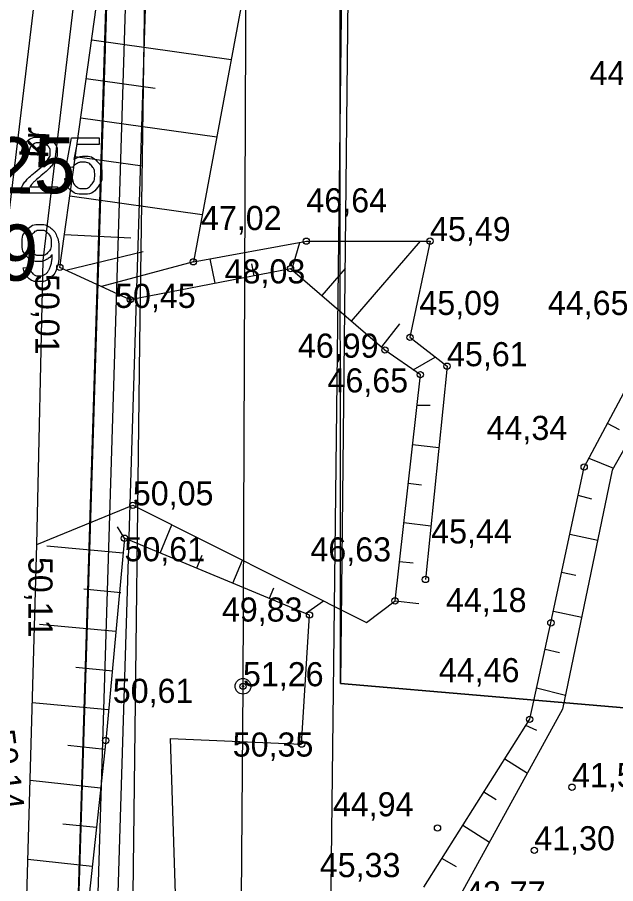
# Model space of a CAD drawing. Extents: x 700746 to 706058, y 6570320 to 6580460.
# Drawn here: x 702833.2 to 702894, y 6575690.9 to 6575779 of the extents above; entities that cross this region are included whole.
import ezdxf

# ---------------------------------------------------------------- set-up
doc = ezdxf.new("R2010")
doc.units = 0
for name, color, linetype in [('illumineerimisjooned', 7, 'Continuous'), ('Kaitsevöönd', 7, 'Continuous'), ('kataster', 7, 'Continuous'), ('KORGUS-EH2000', 7, 'Continuous'), ('KPKAABEL', 7, 'Continuous'), ('Plokid', 7, 'Continuous'), ('POST', 7, 'Continuous'), ('RELJEEF', 7, 'Continuous'), ('TEE', 7, 'Continuous'), ('Tmaad_maeeraldised_kehtivad', 7, 'Continuous'), ('VEEKOGU', 7, 'Continuous'), ('VWX2_MV_PLOKK', 7, 'Continuous')]:
    doc.layers.add(name, color=color, linetype=linetype)

msp = doc.modelspace()

# ---------------------------------------------------------------- linework, layer by layer
at = {"layer": 'illumineerimisjooned'}
msp.add_lwpolyline([(703275.453, 6577071.675), (703358.033, 6576531.935), (703309.575, 6576228.785), (703291.689, 6575965.796), (703292.021, 6575933.773), (703296.797, 6575575.058), (702854.003, 6575511.215), (702839.234, 6575620.766), (702850.34, 6575977.305), (702784.776, 6576064.061), (702784.616, 6576095.834), (702844.434, 6576209.852), (702855.457, 6576267.302), (702846.533, 6576489.405), (702878.886, 6576547.086), (702976.891, 6576643.26), (702915.328, 6577059.558)], dxfattribs=at)
at = {"layer": 'Kaitsevöönd'}
for points in [[(702808.735, 6576109.925), (702830.035, 6576060.935), (702864.499, 6575987.242), (702865.476, 6575983.196), (702867.41, 6575887.926), (702864.438, 6575639.035), (702863.499, 6575550.311), (702871.746, 6575516.763), (703096.25, 6575553.857)], [(703057.554, 6575527.213), (702948.271, 6575509.249), (702866.405, 6575495.727), (702861.964, 6575495.437), (702858.681, 6575497.176), (702855.689, 6575499.88), (702853.951, 6575503.84), (702843.235, 6575549.524), (702845.069, 6575698.167), (702845.649, 6575745.879), (702846.421, 6575800.352), (702847.193, 6575873.756), (702847.193, 6575901.669), (702846.517, 6575932.865), (702845.542, 6575980.609), (702820.936, 6576032.471), (702787.754, 6576109.144)]]:
    msp.add_lwpolyline(points, dxfattribs=at)
at = {"layer": 'kataster'}
msp.add_lwpolyline([(702852.27, 6575508.89), (702837.26, 6575620.73), (702848.38, 6575976.59), (702782.85, 6576063.35), (702782.57, 6576096.37), (702842.53, 6576210.56), (702853.4, 6576267.5), (702844.46, 6576489.93), (702877.29, 6576548.25), (702974.72, 6576643.9), (702913.57, 6577058.07), (702784.04, 6577102.84), (702746.48, 6577248.7), (702719.69, 6577297.36), (702713.81, 6577334.91), (703089.87, 6577211.79), (703231.53, 6577106.55), (703277.36, 6577072.83), (703360.09, 6576531.99), (703311.6, 6576228.52), (703293.62, 6575965.66), (703298.84, 6575573.29)], close=True, dxfattribs=at)
for points in [[(702782.57, 6576096.37), (702782.85, 6576063.35), (702848.38, 6575976.59), (702837.26, 6575620.73), (702852.27, 6575508.89), (703298.84, 6575573.29), (703375.63, 6575584.41), (703375.41, 6575624), (703375.74, 6575634.8), (703375.62, 6575689.75), (703370.21, 6575799.42), (703370.29, 6575828.47), (703365.86, 6576033.99), (703361.97, 6576073.22), (703340.19, 6576155.31)], [(702838.794, 6575763.726), (702838.138, 6575763.813), (702838.69, 6575766.741), (702841.522, 6575766.741), (702841.522, 6575766.072), (702839.249, 6575766.072), (702838.942, 6575764.542)], [(702834.345, 6575765.117), (702833.624, 6575765.19)], [(702838.012, 6575762.61), (702838.746, 6575762.671)], [(702837.26, 6575761.789), (702837.26, 6575761.115), (702833.494, 6575761.115)], [(702834.467, 6575761.789), (702837.26, 6575761.789)], [(702833.779, 6575753.559), (702834.452, 6575753.62)]]:
    msp.add_lwpolyline(points, dxfattribs=at)
for points in [[(702833.494, 6575761.115), (702833.486, 6575761.368), (702833.575, 6575761.602), (702833.719, 6575761.987), (702834.037, 6575762.36), (702834.354, 6575762.733), (702834.952, 6575763.222), (702835.88, 6575763.985), (702836.205, 6575764.43), (702836.531, 6575764.875), (702836.531, 6575765.272), (702836.531, 6575765.688), (702836.234, 6575765.974), (702835.937, 6575766.259), (702835.459, 6575766.259), (702834.955, 6575766.259), (702834.652, 6575765.956), (702834.349, 6575765.653), (702834.345, 6575765.117)], [(702833.624, 6575765.19), (702833.698, 6575765.994), (702834.18, 6575766.416), (702834.662, 6575766.837), (702835.475, 6575766.837), (702836.295, 6575766.837), (702836.773, 6575766.382), (702837.252, 6575765.928), (702837.252, 6575765.255), (702837.252, 6575764.913), (702837.112, 6575764.583), (702836.972, 6575764.253), (702836.648, 6575763.888), (702836.324, 6575763.522), (702835.571, 6575762.885), (702834.941, 6575762.356), (702834.762, 6575762.168), (702834.583, 6575761.979), (702834.467, 6575761.789)], [(702838.942, 6575764.542), (702839.455, 6575764.899), (702840.019, 6575764.899), (702840.765, 6575764.899), (702841.279, 6575764.382), (702841.792, 6575763.864), (702841.792, 6575763.051), (702841.792, 6575762.277), (702841.341, 6575761.712), (702840.792, 6575761.02), (702839.844, 6575761.02), (702839.066, 6575761.02), (702838.574, 6575761.455), (702838.082, 6575761.891), (702838.012, 6575762.61)], [(702838.746, 6575762.671), (702838.828, 6575762.134), (702839.124, 6575761.863), (702839.421, 6575761.593), (702839.843, 6575761.593), (702840.352, 6575761.593), (702840.7, 6575761.975), (702841.049, 6575762.357), (702841.049, 6575762.988), (702841.049, 6575763.589), (702840.714, 6575763.936), (702840.379, 6575764.282), (702839.832, 6575764.282), (702839.492, 6575764.282), (702839.221, 6575764.128), (702838.95, 6575763.973), (702838.794, 6575763.726)], [(702834.452, 6575753.62), (702834.538, 6575753.145), (702834.779, 6575752.93), (702835.019, 6575752.716), (702835.396, 6575752.716), (702835.718, 6575752.716), (702835.962, 6575752.864), (702836.206, 6575753.012), (702836.36, 6575753.259), (702836.514, 6575753.506), (702836.619, 6575753.926), (702836.724, 6575754.346), (702836.724, 6575754.782), (702836.724, 6575754.829), (702836.72, 6575754.922), (702836.511, 6575754.587), (702836.147, 6575754.379), (702835.784, 6575754.171), (702835.361, 6575754.171), (702834.654, 6575754.171), (702834.164, 6575754.684), (702833.675, 6575755.197), (702833.675, 6575756.037), (702833.675, 6575756.903), (702834.186, 6575757.431), (702834.696, 6575757.96), (702835.466, 6575757.96), (702836.021, 6575757.96), (702836.482, 6575757.661), (702836.942, 6575757.361), (702837.181, 6575756.808), (702837.42, 6575756.254), (702837.42, 6575755.205), (702837.42, 6575754.113), (702837.183, 6575753.466), (702836.946, 6575752.819), (702836.478, 6575752.481), (702836.009, 6575752.143), (702835.38, 6575752.143), (702834.712, 6575752.143), (702834.288, 6575752.514), (702833.864, 6575752.886), (702833.779, 6575753.559)], [(702836.642, 6575756.072), (702836.642, 6575756.674), (702836.323, 6575757.028), (702836.004, 6575757.382), (702835.552, 6575757.382), (702835.084, 6575757.382), (702834.74, 6575757.001), (702834.396, 6575756.62), (702834.396, 6575756.013), (702834.396, 6575755.469), (702834.723, 6575755.129), (702835.049, 6575754.788), (702835.533, 6575754.788), (702836.017, 6575754.788), (702836.33, 6575755.129), (702836.642, 6575755.469), (702836.642, 6575756.072)]]:
    msp.add_open_spline(points, degree=3, dxfattribs=at)
at = {"layer": 'KORGUS-EH2000'}
for centre in [(702862.577, 6575756.254), (702875.146, 6575756.258), (702837.505, 6575753.588), (702851.08, 6575754.152), (702860.956, 6575753.455), (702844.673, 6575750.305), (702873.104, 6575746.479), (702870.565, 6575745.185), (702876.87, 6575743.541), (702874.162, 6575742.673), (702890.814, 6575733.297), (702844.929, 6575729.402), (702844.078, 6575726.057), (702874.68, 6575721.867), (702871.589, 6575719.69), (702862.888, 6575718.244), (702887.432, 6575717.455), (702856.125, 6575711.01), (702885.279, 6575707.657), (702842.17, 6575705.495), (702862.086, 6575705.125), (702889.577, 6575700.75), (702875.904, 6575696.596), (702885.74, 6575694.338)]:
    msp.add_circle(centre, 0.32, dxfattribs=at)
at = {"layer": 'KPKAABEL'}
msp.add_lwpolyline([(702819.632, 6576245.483), (702836.589, 6576184.262), (702797.604, 6576109.544), (702828.991, 6576046.164), (702858.934, 6575984.917), (702857.418, 6575888.76), (702856.506, 6575810.457), (702856.125, 6575711.01), (702855.369, 6575615.968), (702854.387, 6575550.184), (702865.017, 6575505.159), (702921.92, 6575514.247), (702993.744, 6575525.722), (703056.422, 6575535.341), (703120.247, 6575545.359), (703173.195, 6575553.732), (703215.558, 6575560.468), (703265.052, 6575567.872), (703307.328, 6575597.7), (703332.603, 6575614.363)], dxfattribs=at)
at = {"layer": 'Plokid'}
for points in [[(702917.129, 6577061.05), (702979.018, 6576642.545), (702880.491, 6576545.858), (702848.554, 6576488.92), (702857.464, 6576267.152), (702846.343, 6576209.185), (702786.618, 6576095.345), (702786.772, 6576064.737), (702852.361, 6575977.948), (702841.238, 6575620.869), (702855.715, 6575513.483), (703019.069, 6575537.036)], [(703072.3, 6576854.63), (703101.31, 6576579.97), (703076.01, 6576303.02), (703067.36, 6576229.67), (703051.03, 6576091.21), (703059.38, 6575886.59), (702981.97, 6575701.33), (702866.03, 6575711.28), (702865.95, 6575985.44), (702842.72, 6576158.42), (702849.095, 6576223.528)]]:
    msp.add_lwpolyline(points, dxfattribs=at)
at = {"layer": 'POST'}
for radius in [0.8, 0.0747]:
    msp.add_circle((702856.125, 6575711.01), radius, dxfattribs=at)
at = {"layer": 'RELJEEF'}
for p, q in [((702840.747, 6575776.701), (702854.925, 6575774.713)), ((702847.19, 6575771.758), (702840.192, 6575772.74)), ((702839.636, 6575768.779), (702853.453, 6575766.841)), ((702845.898, 6575763.861), (702839.08, 6575764.818)), ((702838.525, 6575760.857), (702851.981, 6575758.969)), ((702844.717, 6575756.553), (702837.969, 6575756.895)), ((702861.101, 6575753.33), (702861.903, 6575756.131)), ((702867.165, 6575748.111), (702874.176, 6575756.258)), ((702838.106, 6575753.313), (702845.989, 6575755.191)), ((702851.08, 6575754.152), (702841.742, 6575751.647)), ((702853.29, 6575751.971), (702852.807, 6575754.468)), ((702857.003, 6575753.964), (702857.217, 6575752.731)), ((702866.515, 6575753.488), (702864.133, 6575750.72)), ((702872.037, 6575747.843), (702870.197, 6575745.502)), ((702873.446, 6575743.173), (702875.681, 6575744.468)), ((702875.141, 6575739.559), (702873.814, 6575739.565)), ((702894.406, 6575737.073), (702893.187, 6575737.726)), ((702873.369, 6575735.59), (702876.037, 6575735.292)), ((702891.298, 6575734.2), (702893.802, 6575733.18)), ((702874.279, 6575731.463), (702872.924, 6575731.615)), ((702891.594, 6575730.035), (702890.193, 6575730.387)), ((702872.479, 6575727.64), (702875.232, 6575727.332)), ((702843.324, 6575727.219), (702844.073, 6575725.998)), ((702847.717, 6575724.545), (702848.887, 6575727.419)), ((702889.358, 6575726.475), (702892.199, 6575725.869)), ((702843.937, 6575724.54), (702836.183, 6575725.26)), ((702851.952, 6575724.312), (702851.411, 6575723.011)), ((702855.106, 6575721.476), (702856.077, 6575723.816)), ((702873.432, 6575723.508), (702872.034, 6575723.665)), ((702889.953, 6575722.258), (702888.523, 6575722.564)), ((702839.956, 6575720.925), (702843.697, 6575720.545)), ((702859.231, 6575720.981), (702858.8, 6575719.942)), ((702862.494, 6575718.408), (702864.317, 6575719.688)), ((702871.589, 6575719.69), (702874.02, 6575719.417)), ((702887.688, 6575718.652), (702890.565, 6575718.031)), ((702843.198, 6575716.574), (702835.444, 6575717.294)), ((702888.292, 6575714.425), (702886.836, 6575714.743)), ((702839.146, 6575712.967), (702842.887, 6575712.586)), ((702885.978, 6575710.837), (702888.91, 6575710.093)), ((702842.459, 6575708.609), (702834.704, 6575709.328)), ((702886.013, 6575706.52), (702884.882, 6575707.027)), ((702838.336, 6575705.008), (702842.077, 6575704.627)), ((702882.748, 6575703.644), (702885.046, 6575702.194)), ((702841.649, 6575700.65), (702834.485, 6575701.42)), ((702881.865, 6575699.472), (702880.613, 6575700.261)), ((702837.797, 6575697.041), (702841.221, 6575696.673)), ((702878.479, 6575696.878), (702881.187, 6575695.169)), ((702840.793, 6575692.696), (702834.262, 6575693.398)), ((702877.841, 6575692.649), (702876.344, 6575693.496))]:
    msp.add_line(p, q, dxfattribs=at)
for points in [[(702871.589, 6575719.69), (702874.162, 6575742.673), (702870.565, 6575745.185), (702860.956, 6575753.455), (702844.673, 6575750.305), (702837.505, 6575753.588), (702842.098, 6575786.333), (702840.272, 6575807.444), (702853.436, 6575807.886), (702859.35, 6575808.801), (702870.938, 6575805.69), (702872.009, 6575807.48), (702858.699, 6575809.522), (702857.068, 6575811.593), (702851.253, 6575813.293), (702841.691, 6575818.092), (702843.708, 6575841.79), (702844.92, 6575862.739), (702851.277, 6575867.185), (702864.837, 6575861.887)], [(702865.774, 6575857.932), (702864.619, 6575855.386), (702866.231, 6575833.66), (702863.097, 6575820.039), (702879.935, 6575816.131), (702881.058, 6575800.72), (702871.833, 6575799.253), (702858.602, 6575794.375), (702851.08, 6575754.152), (702862.577, 6575756.254), (702875.146, 6575756.258), (702873.104, 6575746.479), (702876.87, 6575743.541), (702874.68, 6575721.867)], [(702874.512, 6575690.592), (702885.279, 6575707.657), (702887.432, 6575717.455), (702890.814, 6575733.297), (702897.026, 6575744.892), (702902.126, 6575769.488), (702911.243, 6575780.672), (702915.186, 6575790.449), (702915.469, 6575796.627), (702923.765, 6575822.645), (702908.57, 6575835.71)], [(702835.151, 6575725.409), (702844.929, 6575729.402), (702868.679, 6575717.503), (702871.589, 6575719.69)], [(702849.439, 6575684.65), (702848.745, 6575705.714), (702862.086, 6575705.125), (702862.888, 6575718.244), (702844.078, 6575726.057), (702842.17, 6575705.495), (702840.142, 6575686.638), (702843.776, 6575683.256), (702849.439, 6575684.65)]]:
    msp.add_lwpolyline(points, dxfattribs=at)
at = {"layer": 'TEE'}
for points in [[(702830.027, 6575684.968), (702831.152, 6575725.51), (702831.817, 6575754.565), (702835.347, 6575784.08), (702835.644, 6575813.072), (702839.086, 6575843.28), (702841.092, 6575866.647), (702842.664, 6575897.87), (702846.655, 6575935.935), (702841.574, 6575967.648), (702838.099, 6575974.634), (702830.651, 6575991.099), (702817.57, 6576005.083), (702798.577, 6576023.982), (702784.187, 6576040.099), (702774.299, 6576061.057), (702771.808, 6576073.949), (702774.342, 6576099.093)], [(702834.025, 6575684.858), (702835.151, 6575725.409), (702835.811, 6575754.281), (702839.345, 6575783.821), (702839.641, 6575812.824), (702843.066, 6575842.882), (702845.083, 6575866.375), (702846.653, 6575897.561), (702850.688, 6575936.045), (702845.427, 6575968.882), (702841.714, 6575976.348), (702834.023, 6575993.349), (702820.442, 6576007.868), (702801.482, 6576026.734), (702787.557, 6576042.33), (702778.131, 6576062.309), (702775.846, 6576074.132), (702778.245, 6576097.929)]]:
    msp.add_lwpolyline(points, dxfattribs=at)
at = {"layer": 'Tmaad_maeeraldised_kehtivad'}
msp.add_lwpolyline([(703277.305, 6577072.795), (703360.057, 6576531.928), (703311.564, 6576228.559), (703293.69, 6575965.739), (703294.021, 6575933.797), (703298.82, 6575573.329), (702852.291, 6575508.948), (702837.23, 6575620.663), (702848.319, 6575976.662), (702782.779, 6576063.386), (702782.613, 6576096.322), (702842.526, 6576210.519), (702853.449, 6576267.453), (702844.512, 6576489.89), (702877.282, 6576548.313), (702974.764, 6576643.974), (702913.527, 6577058.065)], dxfattribs=at)
at = {"layer": 'VEEKOGU'}
msp.add_lwpolyline([(702958.218, 6575889.272), (702958.059, 6575889.258), (702954.605, 6575888.27), (702948.294, 6575884.892), (702933.624, 6575863.588), (702930.278, 6575837.16), (702934.021, 6575828.451), (702932.487, 6575821.044), (702937.325, 6575809.272), (702934.599, 6575804.415), (702920.203, 6575795.023), (702917.021, 6575790.184), (702912.522, 6575779.383), (702904.861, 6575766.699), (702900.619, 6575756.999), (702900.7, 6575745.439), (702893.678, 6575732.96), (702888.619, 6575708.698), (702877.905, 6575689.195)], dxfattribs=at)
msp.add_lwpolyline([(702958.218, 6575889.272), (702958.059, 6575889.258), (702954.605, 6575888.27), (702948.294, 6575884.892), (702933.624, 6575863.588), (702930.278, 6575837.16), (702934.021, 6575828.451), (702932.487, 6575821.044), (702937.325, 6575809.272), (702934.599, 6575804.415), (702920.203, 6575795.023), (702917.021, 6575790.184), (702912.522, 6575779.383), (702904.861, 6575766.699), (702900.619, 6575756.999), (702900.7, 6575745.439), (702893.678, 6575732.96), (702888.619, 6575708.698), (702877.905, 6575689.195)], dxfattribs=at)
at = {"layer": 'VWX2_MV_PLOKK'}
msp.add_lwpolyline([(703145.59, 6575981.92), (703053.36, 6575698.14), (703018.17, 6575532.81), (702852.27, 6575508.89), (702837.26, 6575620.73), (702848.38, 6575976.59), (702782.85, 6576063.35), (702782.57, 6576096.37), (702842.53, 6576210.56), (702853.4, 6576267.5), (702842.72, 6576158.42), (702865.95, 6575985.44), (702867.94, 6575888.34), (702866.03, 6575711.28), (702981.97, 6575701.33), (703059.38, 6575886.59), (703051.03, 6576091.21), (703067.36, 6576229.67), (703076.01, 6576303.02), (703101.31, 6576579.97), (703072.3, 6576854.63), (703072.13, 6576856.26), (703120.61, 6576749.6), (703123.04, 6576234.88)], close=True, dxfattribs=at)
msp.add_lwpolyline([(703145.59, 6575981.92), (703053.36, 6575698.14), (703018.17, 6575532.81), (702852.27, 6575508.89), (702837.26, 6575620.73), (702848.38, 6575976.59), (702782.85, 6576063.35), (702782.57, 6576096.37), (702842.53, 6576210.56), (702853.4, 6576267.5), (702842.72, 6576158.42), (702865.95, 6575985.44), (702867.94, 6575888.34), (702866.03, 6575711.28), (702981.97, 6575701.33), (703059.38, 6575886.59), (703051.03, 6576091.21), (703067.36, 6576229.67), (703076.01, 6576303.02), (703101.31, 6576579.97), (703072.3, 6576854.63), (703072.13, 6576856.26), (703120.61, 6576749.6), (703123.04, 6576234.88)], close=True, dxfattribs=at)

# ---------------------------------------------------------------- texts
at = {"layer": 'kataster'}
for s, p in [('Ahtme metskond 25', (702771.298, 6575761.115)), ('22901:001:0239', (702780.224, 6575752.238))]:
    msp.add_text(s, height=5.7, dxfattribs=at).set_placement(p)
at = {"layer": 'KORGUS-EH2000'}
for s, p in [('44,48 ', (702891.37, 6575772.119)), ('46,64 ', (702862.577, 6575759.184)), ('47,02 ', (702851.856, 6575757.381)), ('45,49 ', (702875.146, 6575756.258)), ('48,03 ', (702854.263, 6575751.96)), ('50,45 ', (702843.119, 6575749.467)), ('45,09 ', (702874.06, 6575748.751)), ('44,65 ', (702887.124, 6575748.748)), ('46,99 ', (702861.712, 6575744.408)), ('45,61 ', (702876.87, 6575743.541)), ('46,65 ', (702864.72, 6575740.879)), ('44,34 ', (702880.895, 6575736.048)), ('50,05 ', (702844.929, 6575729.402)), ('45,44 ', (702875.261, 6575725.523)), ('50,61 ', (702844.078, 6575723.714)), ('46,63 ', (702862.984, 6575723.696)), ('44,18 ', (702876.761, 6575718.548)), ('49,83 ', (702853.984, 6575717.586)), ('51,26 ', (702856.125, 6575711.01)), ('44,46 ', (702876.043, 6575711.424)), ('50,61 ', (702842.887, 6575709.322)), ('50,35 ', (702855.08, 6575703.862)), ('41,58 ', (702889.577, 6575700.75)), ('44,94 ', (702865.268, 6575697.792)), ('41,30 ', (702885.74, 6575694.338)), ('45,33 ', (702863.935, 6575691.608)), ('42,77 ', (702878.703, 6575688.731))]:
    msp.add_text(s, height=2.45, dxfattribs=at).set_placement(p)
for s, rotation, p in [('50,01 ', 270, (702835.009, 6575752.919)), ('50,11 ', 270, (702834.312, 6575724.161)), ('50,14 ', 277.3642, (702830.453, 6575706.464))]:
    msp.add_text(s, height=2.45, rotation=rotation, dxfattribs=at).set_placement(p)
at = {"layer": 'TEE'}
msp.add_text('kr', height=2.8, rotation=87.16147, dxfattribs=at).set_placement((702836.318, 6575764.652))

doc.saveas('drawing.dxf')
